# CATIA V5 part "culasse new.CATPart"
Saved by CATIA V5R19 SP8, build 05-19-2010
Part number: culasse
Bounding box of the stored display mesh (mm): x -25.5 to 0, y -8 to 20, z 0 to 171
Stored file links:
  E:\Catia parts\GLOCK\Ensemble culasse\culasse new.CATPart
  C:\Users\Arthur\Desktop\Catia parts\GLOCK\Ensemble culasse\Culasse.CATPart
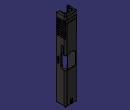
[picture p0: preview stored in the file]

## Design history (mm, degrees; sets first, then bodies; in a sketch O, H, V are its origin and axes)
Body1 (main body)
  Solid1: solid without history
